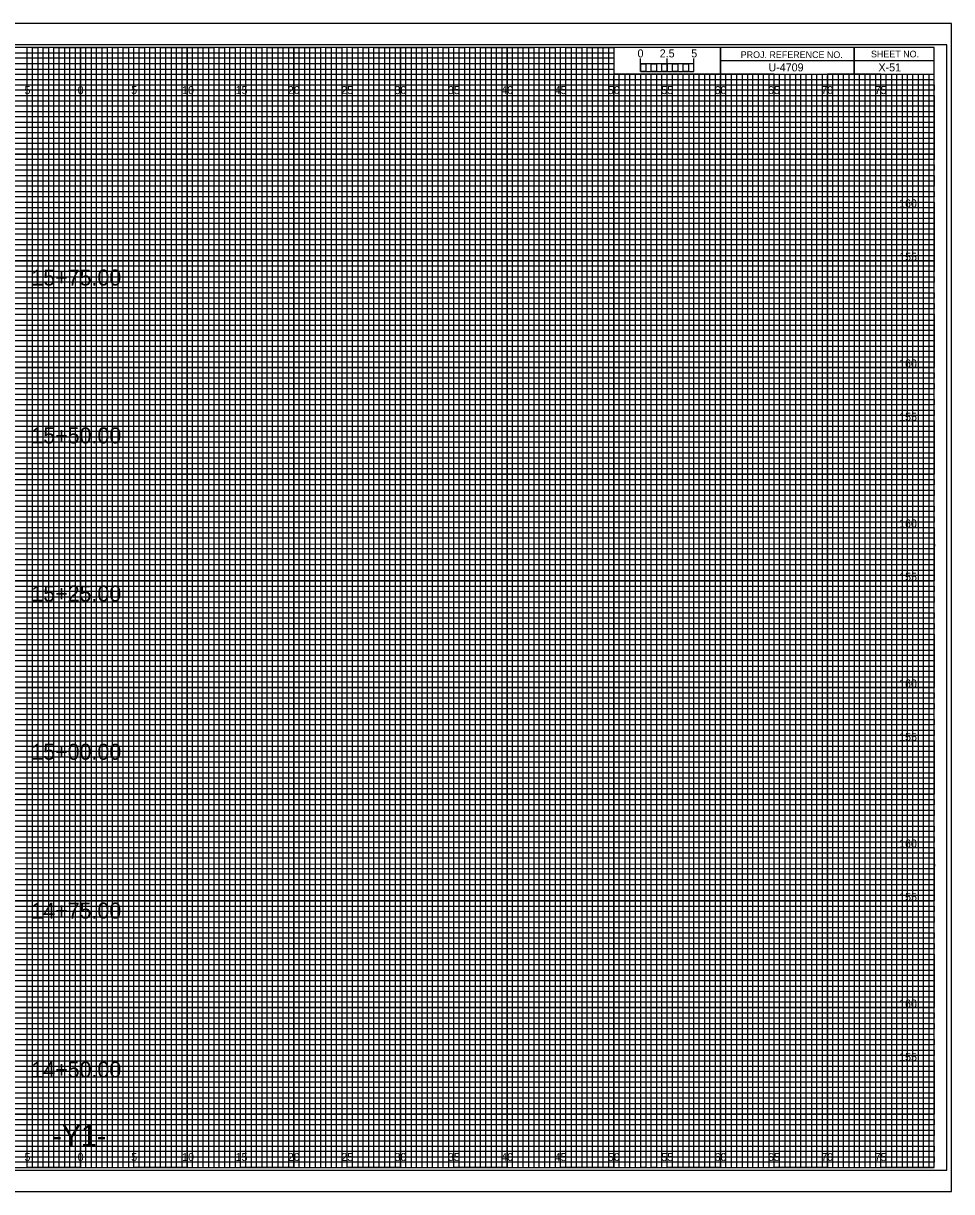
# Model space of a CAD drawing. Extents: x -7 to 162, y 328 to 437.
# Drawn here: x 74.6 to 161.7, y 327.7 to 437.2 of the extents above; entities that cross this region are included whole.
import ezdxf

# ---------------------------------------------------------------- set-up
doc = ezdxf.new("R2010")
doc.units = 0
for name, color, linetype in [('Prop CMT Conc Surface', 7, 'Continuous'), ('Prop CMT Pvmt Course 1', 7, 'Continuous'), ('Prop CMT Pvmt Surface Shoulder', 7, 'Continuous'), ('Prop CMT Pvmt Wedge Surface 3', 7, 'Continuous'), ('Prop CMT Shld Paved Course 1', 7, 'Continuous'), ('Prop CMT Shld Paved Course 2', 7, 'Continuous'), ('Prop CMT Shld Paved Course 3', 7, 'Continuous'), ('Prop CMT Slope Grass', 7, 'Continuous'), ('Prop XS Alignment Label', 7, 'Continuous'), ('Prop XS Bar Scale Labels', 7, 'Continuous'), ('Prop XS Ditch Standard Text', 7, 'Continuous'), ('Prop XS Earthwork Shape', 7, 'Continuous'), ('Prop XS Hydro Elevations', 7, 'Continuous'), ('Prop XS Project Number', 7, 'Continuous'), ('Prop XS SE Text', 7, 'Continuous'), ('Prop XS Sheet Number', 7, 'Continuous'), ('Prop XS Side Slope Text', 7, 'Continuous')]:
    doc.layers.add(name, color=color, linetype=linetype)

msp = doc.modelspace()

# ---------------------------------------------------------------- linework, layer by layer
at = {"layer": 'Prop CMT Conc Surface'}
for points in [[(72.5, 330), (77.5, 330), (77.5, 435), (82.5, 435), (82.5, 330), (87.5, 330), (87.5, 435), (92.5, 435), (92.5, 330), (97.5, 330), (97.5, 435), (102.5, 435), (102.5, 330), (107.5, 330), (107.5, 435), (112.5, 435), (112.5, 330), (117.5, 330), (117.5, 435), (122.5, 435), (122.5, 330), (127.5, 330), (127.5, 435), (129.97, 435), (130, 435), (130, 432.5), (132.5, 432.5), (132.5, 330), (137.5, 330), (137.5, 432.5), (142.5, 432.5), (142.5, 330), (147.5, 330), (147.5, 432.5), (152.5, 432.5), (152.5, 330), (157.5, 330), (157.5, 432.5)], [(0, 432.5), (137.5, 432.5)], [(0, 422.5), (160, 422.5), (160, 427.5), (0, 427.5)], [(0, 412.5), (160, 412.5), (160, 417.5), (0, 417.5)], [(0, 402.5), (160, 402.5), (160, 407.5), (0, 407.5)], [(0, 392.5), (160, 392.5), (160, 397.5), (0, 397.5)], [(0, 382.5), (160, 382.5), (160, 387.5), (0, 387.5)], [(0, 372.5), (160, 372.5), (160, 377.5), (0, 377.5)], [(0, 362.5), (160, 362.5), (160, 367.5), (0, 367.5)], [(0, 352.5), (160, 352.5), (160, 357.5), (0, 357.5)], [(0, 342.5), (160, 342.5), (160, 347.5), (0, 347.5)], [(0, 332.5), (160, 332.5), (160, 337.5), (0, 337.5)]]:
    msp.add_lwpolyline(points, dxfattribs=at)
at = {"layer": 'Prop CMT Pvmt Course 1'}
for p, q in [((75, 435), (70, 435)), ((75, 330), (75, 435)), ((85, 435), (80, 435)), ((80, 435), (80, 330)), ((85, 330), (85, 435)), ((95, 435), (90, 435)), ((90, 435), (90, 330)), ((95, 330), (95, 435)), ((105, 435), (100, 435)), ((100, 435), (100, 330)), ((105, 330), (105, 435)), ((115, 435), (110, 435)), ((110, 435), (110, 330)), ((115, 330), (115, 435)), ((125, 435), (120, 435)), ((120, 435), (120, 330)), ((125, 330), (125, 435)), ((130, 435), (130, 330)), ((135, 330), (135, 432.5)), ((145, 432.5), (140, 432.5)), ((140, 432.5), (140, 330)), ((145, 330), (145, 432.5)), ((155, 432.5), (150, 432.5)), ((150, 432.5), (150, 330)), ((155, 330), (155, 432.5)), ((80, 330), (75, 330)), ((90, 330), (85, 330)), ((100, 330), (95, 330)), ((110, 330), (105, 330)), ((120, 330), (115, 330)), ((130, 330), (125, 330)), ((140, 330), (135, 330)), ((150, 330), (145, 330)), ((160, 330), (155, 330)), ((160, 330), (160, 330))]:
    msp.add_line(p, q, dxfattribs=at)
for points in [[(0, 430), (160, 430), (160, 425), (0, 425)], [(0, 420), (160, 420), (160, 415), (0, 415)], [(0, 410), (160, 410), (160, 405), (0, 405)], [(0, 400), (160, 400), (160, 395), (0, 395)], [(0, 390), (160, 390), (160, 385), (0, 385)], [(0, 380), (160, 380), (160, 375), (0, 375)], [(0, 370), (160, 370), (160, 365), (0, 365)], [(0, 360), (160, 360), (160, 355), (0, 355)], [(0, 350), (160, 350), (160, 345), (0, 345)], [(0, 340), (160, 340), (160, 335), (0, 335)]]:
    msp.add_lwpolyline(points, dxfattribs=at)
at = {"layer": 'Prop CMT Pvmt Surface Shoulder'}
msp.add_lwpolyline([(-6.7, 327.75), (161.65, 327.75), (161.65, 437.25), (-6.7, 437.25)], close=True, dxfattribs=at)
at = {"layer": 'Prop CMT Shld Paved Course 1'}
for p, q in [((152.5, 435), (152.5, 432.5)), ((152.5, 432.5), (152.5, 435)), ((160, 433.75), (140, 433.75)), ((140, 433.75), (140, 432.5)), ((140, 432.5), (160, 432.5))]:
    msp.add_line(p, q, dxfattribs=at)
for points in [[(160, 435), (0, 435), (0, 330), (160, 330)], [(140, 435), (130, 435), (130, 432.51), (140, 432.51)], [(160, 435), (140, 435), (140, 432.5), (160, 432.5)]]:
    msp.add_lwpolyline(points, close=True, dxfattribs=at)
at = {"layer": 'Prop CMT Shld Paved Course 2'}
for p, q in [((133.5, 432.5), (133, 432.5)), ((133, 432.5), (133, 330)), ((133.5, 330), (133.5, 432.5)), ((134.5, 432.5), (134, 432.5)), ((134, 432.5), (134, 330)), ((134.5, 330), (134.5, 432.5)), ((133, 330), (132.5, 330)), ((134, 330), (133.5, 330))]:
    msp.add_line(p, q, dxfattribs=at)
for points in [[(75, 330), (75.5, 330), (75.5, 435), (76, 435), (76, 330)], [(76, 330), (76.5, 330), (76.5, 435), (77, 435), (77, 330)], [(77.5, 330), (78, 330), (78, 435), (78.5, 435), (78.5, 330)], [(78.5, 330), (79, 330), (79, 435), (79.5, 435), (79.5, 330)], [(80, 330), (80.5, 330), (80.5, 435), (81, 435), (81, 330)], [(81, 330), (81.5, 330), (81.5, 435), (82, 435), (82, 330)], [(82.5, 330), (83, 330), (83, 435), (83.5, 435), (83.5, 330)], [(83.5, 330), (84, 330), (84, 435), (84.5, 435), (84.5, 330)], [(85, 330), (85.5, 330), (85.5, 435), (86, 435), (86, 330)], [(86, 330), (86.5, 330), (86.5, 435), (87, 435), (87, 330)], [(87.5, 330), (88, 330), (88, 435), (88.5, 435), (88.5, 330)], [(88.5, 330), (89, 330), (89, 435), (89.5, 435), (89.5, 330)], [(90, 330), (90.5, 330), (90.5, 435), (91, 435), (91, 330)], [(91, 330), (91.5, 330), (91.5, 435), (92, 435), (92, 330)], [(92.5, 330), (93, 330), (93, 435), (93.5, 435), (93.5, 330)], [(93.5, 330), (94, 330), (94, 435), (94.5, 435), (94.5, 330)], [(95, 330), (95.5, 330), (95.5, 435), (96, 435), (96, 330)], [(96, 330), (96.5, 330), (96.5, 435), (97, 435), (97, 330)], [(97.5, 330), (98, 330), (98, 435), (98.5, 435), (98.5, 330)], [(98.5, 330), (99, 330), (99, 435), (99.5, 435), (99.5, 330)], [(100, 330), (100.5, 330), (100.5, 435), (101, 435), (101, 330)], [(101, 330), (101.5, 330), (101.5, 435), (102, 435), (102, 330)], [(102.5, 330), (103, 330), (103, 435), (103.5, 435), (103.5, 330)], [(103.5, 330), (104, 330), (104, 435), (104.5, 435), (104.5, 330)], [(105, 330), (105.5, 330), (105.5, 435), (106, 435), (106, 330)], [(106, 330), (106.5, 330), (106.5, 435), (107, 435), (107, 330)], [(107.5, 330), (108, 330), (108, 435), (108.5, 435), (108.5, 330)], [(108.5, 330), (109, 330), (109, 435), (109.5, 435), (109.5, 330)], [(110, 330), (110.5, 330), (110.5, 435), (111, 435), (111, 330)], [(111, 330), (111.5, 330), (111.5, 435), (112, 435), (112, 330)], [(112.5, 330), (113, 330), (113, 435), (113.5, 435), (113.5, 330)], [(113.5, 330), (114, 330), (114, 435), (114.5, 435), (114.5, 330)], [(115, 330), (115.5, 330), (115.5, 435), (116, 435), (116, 330)], [(116, 330), (116.5, 330), (116.5, 435), (117, 435), (117, 330)], [(117.5, 330), (118, 330), (118, 435), (118.5, 435), (118.5, 330)], [(118.5, 330), (119, 330), (119, 435), (119.5, 435), (119.5, 330)], [(120, 330), (120.5, 330), (120.5, 435), (121, 435), (121, 330)], [(121, 330), (121.5, 330), (121.5, 435), (122, 435), (122, 330)], [(122.5, 330), (123, 330), (123, 435), (123.5, 435), (123.5, 330)], [(123.5, 330), (124, 330), (124, 435), (124.5, 435), (124.5, 330)], [(125, 330), (125.5, 330), (125.5, 435), (126, 435), (126, 330)], [(126, 330), (126.5, 330), (126.5, 435), (127, 435), (127, 330)], [(127.5, 330), (128, 330), (128, 435), (128.5, 435), (128.5, 330)], [(128.5, 330), (129, 330), (129, 435), (129.5, 435), (129.5, 330)], [(130, 330), (130.5, 330), (130.5, 432.5), (131.01, 432.5), (131.01, 330)], [(131, 330), (131.5, 330), (131.5, 432.5), (132, 432.5), (132, 330)], [(135, 330), (135.49, 330), (135.49, 432.5), (136, 432.5), (136, 330)], [(136, 330), (136.5, 330), (136.5, 432.5), (137.03, 432.5), (137.03, 330)], [(137.5, 330), (138, 330), (138, 432.5), (138.5, 432.5), (138.5, 330)], [(138.5, 330), (139, 330), (139, 432.5), (139.5, 432.5), (139.5, 330)], [(140, 330), (140.5, 330), (140.5, 432.5), (141, 432.5), (141, 330)], [(141, 330), (141.5, 330), (141.5, 432.5), (142, 432.5), (142, 330)], [(142.5, 330), (143, 330), (143, 432.5), (143.5, 432.5), (143.5, 330)], [(143.5, 330), (144, 330), (144, 432.5), (144.5, 432.5), (144.5, 330)], [(145, 330), (145.5, 330), (145.5, 432.5), (146, 432.5), (146, 330)], [(146, 330), (146.5, 330), (146.5, 432.5), (147, 432.5), (147, 330)], [(147.5, 330), (148, 330), (148, 432.5), (148.5, 432.5), (148.5, 330)], [(148.5, 330), (149, 330), (149, 432.5), (149.5, 432.5), (149.5, 330)], [(150, 330), (150.5, 330), (150.5, 432.5), (151, 432.5), (151, 330)], [(151, 330), (151.5, 330), (151.5, 432.5), (152, 432.5), (152, 330)], [(152.5, 330), (153, 330), (153, 432.5), (153.5, 432.5), (153.5, 330)], [(153.5, 330), (154, 330), (154, 432.5), (154.5, 432.5), (154.5, 330)], [(155, 330), (155.5, 330), (155.5, 432.5), (156, 432.5), (156, 330)], [(156, 330), (156.5, 330), (156.5, 432.5), (157, 432.5), (157, 330)], [(157.5, 330), (158, 330), (158, 432.5), (158.5, 432.5), (158.5, 330)], [(158.5, 330), (159, 330), (159, 432.5), (159.5, 432.5), (159.5, 330)]]:
    msp.add_lwpolyline(points, dxfattribs=at)
at = {"layer": 'Prop CMT Shld Paved Course 3'}
for p, q in [((132.5, 432.75), (132.5, 433.95)), ((132.5, 433.45), (132.5, 433.95)), ((135, 432.75), (135, 433.95)), ((137.5, 432.75), (137.5, 433.95)), ((137.5, 433.45), (137.5, 433.95))]:
    msp.add_line(p, q, dxfattribs=at)
for points in [[(137.5, 433.45), (132.5, 433.45), (132.5, 432.75), (137.5, 432.75)], [(132.5, 433.45), (133, 433.45), (133, 432.75), (132.5, 432.75)], [(133.5, 433.45), (134, 433.45), (134, 432.75), (133.5, 432.75)], [(134.5, 433.45), (135, 433.45), (135, 432.75), (134.5, 432.75)], [(135.5, 433.45), (136, 433.45), (136, 432.75), (135.5, 432.75)], [(136.5, 433.45), (137, 433.45), (137, 432.75), (136.5, 432.75)]]:
    msp.add_lwpolyline(points, close=True, dxfattribs=at)
at = {"layer": 'Prop CMT Slope Grass'}
for p, q in [((0, 434.5), (130, 434.5)), ((130, 433.99), (0, 433.99)), ((130, 434.5), (130, 433.99)), ((0, 433.5), (130, 433.5)), ((130, 432.94), (0, 432.94)), ((130, 433.5), (130, 432.94)), ((0, 432), (160, 432))]:
    msp.add_line(p, q, dxfattribs=at)
for points in [[(0, 431.5), (135, 431.5), (160, 431.5), (160, 431), (0, 431)], [(0, 430.5), (160, 430.5), (160, 429.5), (0, 429.5)], [(0, 429), (160, 429), (160, 428.5), (0, 428.49)], [(0, 428), (160, 428), (160, 427), (0, 427)], [(0, 426.5), (160, 426.5), (160, 426), (0, 426)], [(0, 425.5), (160, 425.5), (160, 424.5), (0, 424.5)], [(0, 424), (160, 424), (160, 423.5), (0, 423.5)], [(0, 423), (160, 423), (160, 422), (0, 422)], [(0, 421.5), (160, 421.5), (160, 421), (0, 421)], [(0, 420.5), (160, 420.5), (160, 419.5), (0, 419.5)], [(0, 419), (160, 419), (160, 418.5), (0, 418.5)], [(0, 418), (160, 418), (160, 416.98), (160, 416.5), (160, 416), (0, 416)], [(0, 417), (160, 417), (160, 416.5), (0, 416.5)], [(0, 415.5), (160, 415.5), (160, 414.5), (0, 414.51)], [(0, 414.51), (160, 414.5), (160, 414), (0, 414)], [(0, 413.5), (160, 413.5), (160, 413), (0, 413)], [(0, 412), (160, 412), (160, 411.5), (0, 411.5)], [(0, 411), (160, 411), (160, 410.5), (0, 410.5)], [(-0.04, 409.44), (160, 409.44), (160, 408.94), (-0.04, 408.94)], [(0, 408.5), (160, 408.5), (160, 408), (0, 408)], [(0, 407), (160, 407), (160, 406.5), (0, 406.5)], [(0, 406), (160, 406), (160, 405.5), (0, 405.5)], [(0, 404.5), (160, 404.5), (160, 404), (0, 404)], [(0, 403.5), (160, 403.5), (160, 403), (0, 403)], [(0, 402), (160, 402), (160, 401.5), (0, 401.5)], [(0, 401), (160, 401), (160, 400.5), (0, 400.5)], [(0, 399.5), (160, 399.5), (160, 398.99), (0, 399)], [(0, 398.5), (160, 398.5), (160, 398), (0, 398)], [(0, 397), (160, 397), (160, 396.5), (0, 396.5)], [(0, 396), (160, 396), (160, 395.5), (0, 395.5)], [(0, 394.5), (160, 394.5), (160, 394), (0, 394)], [(0, 393.5), (160, 393.5), (160, 393), (0, 393)], [(0, 392), (160, 392), (160, 391.5), (0, 391.5)], [(0, 391), (160, 391), (160, 390.5), (0, 390.5)], [(0, 389.5), (160, 389.5), (160, 389), (0, 389)], [(0, 388.5), (160.03, 388.45), (160, 388), (0, 388)], [(0, 387), (160, 387), (160, 386.5), (0, 386.5)], [(0, 386), (160, 386), (160, 385.5), (0, 385.5)], [(0, 384.5), (160, 384.5), (160, 384), (0, 384)], [(0, 383.5), (160, 383.5), (160, 383), (0, 383)], [(0, 382), (160, 382), (160, 381.5), (0, 381.5)], [(0, 381), (160, 381), (160, 380.5), (0, 380.5)], [(0, 379.5), (160, 379.5), (160, 379), (0, 379)], [(0, 378.5), (160, 378.5), (160, 378), (0, 378)], [(0, 377), (160, 377), (160, 376.5), (0, 376.5)], [(0, 376), (160, 376), (160, 375.5), (0, 375.5)], [(0, 374.5), (160, 374.5), (160, 374), (0, 374)], [(0, 373.5), (160, 373.5), (160, 373), (0, 373)], [(0, 372), (160, 372), (160, 371.5), (0, 371.5)], [(0, 371), (160, 371), (160, 370.5), (0, 370.5)], [(0, 369.5), (160, 369.5), (160, 368.99), (0, 369)], [(0, 368.5), (160, 368.5), (160, 368), (0, 368)], [(0, 367), (160, 367), (160, 366.5), (0, 366.5)], [(0, 366), (160, 366), (160, 365.5), (0, 365.5)], [(0, 364.5), (160, 364.5), (160, 364), (0, 364)], [(0, 363.5), (160, 363.5), (160, 363), (0, 363)], [(0, 362), (160, 362), (160, 361.5), (0, 361.5)], [(0, 361), (160, 361), (160, 360.5), (0, 360.5)], [(0, 359.5), (160, 359.5), (160, 359), (0, 359)], [(0, 358.5), (160.03, 358.45), (160, 358), (0, 358)], [(0, 357), (160, 357), (160, 356.5), (0, 356.5)], [(0, 356), (160, 356), (160, 355.5), (0, 355.5)], [(0, 354.5), (160, 354.5), (160, 354), (0, 354)], [(0, 353.5), (160, 353.5), (160, 353), (0, 353)], [(0, 352), (160, 352), (160, 351.5), (0, 351.5)], [(0, 351), (160, 351), (160, 350.5), (0, 350.5)], [(0, 349.5), (160, 349.5), (160, 349), (0, 349)], [(0, 348.5), (160, 348.5), (160, 348), (0, 348)], [(0, 347), (160, 347), (160, 346.5), (0, 346.5)], [(0, 346), (160, 346), (160, 345.5), (0, 345.5)], [(0, 344.5), (160, 344.5), (160, 344), (0, 344)], [(0, 343.5), (160, 343.5), (160, 343), (0, 343)], [(0, 342), (160, 342), (160, 341.5), (0, 341.5)], [(0, 341), (160, 341), (160, 340.5), (0, 340.5)], [(0, 339.5), (160, 339.5), (160, 339), (0, 339)], [(0, 338.5), (160, 338.5), (160, 338), (0, 338)], [(0, 337), (160, 337), (160, 336.5), (0, 336.5)], [(0, 336), (160, 336), (160, 335.5), (0, 335.5)], [(0, 334.5), (160, 334.5), (160, 334), (0, 334)], [(0, 333.5), (160, 333.5), (160, 333), (0, 333)], [(0, 332), (160, 332), (160, 331.5), (0, 331.5)], [(0, 331), (160, 331), (160, 330.5), (0, 330.5)]]:
    msp.add_lwpolyline(points, dxfattribs=at)
at = {"layer": 'Prop XS Hydro Elevations'}
for p, q in [((161.65, 437.25), (-6.7, 437.25)), ((-6.7, 327.75), (161.65, 327.75))]:
    msp.add_line(p, q, dxfattribs=at)
at = {"layer": 'Prop XS SE Text'}
msp.add_lwpolyline([(-5.4, 329.75), (161.2, 329.75), (161.2, 435.25), (-5.4, 435.25)], close=True, dxfattribs=at)
at = {"layer": 'Prop XS Side Slope Text'}
for p, q in [((75, 330), (75, 435)), ((80, 330), (80, 435)), ((85, 330), (85, 435)), ((90, 330), (90, 435)), ((95, 330), (95, 435)), ((100, 330), (100, 435)), ((105, 330), (105, 435)), ((110, 330), (110, 435)), ((115, 330), (115, 435)), ((120, 330), (120, 435)), ((125, 330), (125, 435)), ((130, 330), (130, 432.34)), ((135, 330), (135, 432.34)), ((140, 330), (140, 432.34)), ((145, 330), (145, 432.34)), ((150, 330), (150, 432.34)), ((155, 330), (155, 432.34)), ((0, 430), (160, 430)), ((0, 425), (160, 425)), ((0, 420), (160, 420)), ((0, 415), (160, 415)), ((0, 410), (160, 410)), ((0, 405), (160, 405)), ((0, 400), (160, 400)), ((0, 395), (160, 395)), ((0, 390), (160, 390)), ((0, 385), (160, 385)), ((0, 380), (160, 380)), ((0, 375), (160, 375)), ((0, 370), (160, 370)), ((0, 365), (160, 365)), ((0, 360), (160, 360)), ((0, 355), (160, 355)), ((0, 350), (160, 350)), ((0, 345), (160, 345)), ((0, 340), (160, 340)), ((0, 335), (160, 335))]:
    msp.add_line(p, q, dxfattribs=at)

# ---------------------------------------------------------------- texts
at = {"layer": 'Prop CMT Pvmt Wedge Surface 3'}
for s, p in [('5', (74.74, 430.62)), ('0', (79.73, 430.62)), ('0', (79.73, 430.62)), ('5', (84.74, 430.62)), ('10', (89.52, 430.62)), ('15', (94.53, 430.62)), ('20', (99.43, 430.62)), ('25', (104.44, 430.62)), ('30', (109.43, 430.62)), ('35', (114.44, 430.62)), ('40', (119.43, 430.62)), ('45', (124.44, 430.62)), ('50', (129.43, 430.62)), ('55', (134.44, 430.62)), ('60', (139.43, 430.62)), ('65', (144.44, 430.62)), ('70', (149.43, 430.62)), ('75', (154.44, 430.62)), ('5', (74.74, 330.62)), ('0', (79.73, 330.62)), ('0', (79.73, 330.62)), ('5', (84.74, 330.62)), ('10', (89.52, 330.62)), ('15', (94.53, 330.62)), ('20', (99.43, 330.62)), ('25', (104.44, 330.62)), ('30', (109.43, 330.62)), ('35', (114.44, 330.62)), ('40', (119.43, 330.62)), ('45', (124.44, 330.62)), ('50', (129.43, 330.62)), ('55', (134.44, 330.62)), ('60', (139.43, 330.62)), ('65', (144.44, 330.62)), ('70', (149.43, 330.62)), ('75', (154.44, 330.62))]:
    msp.add_text(s, height=0.75, dxfattribs=at).set_placement(p)
at = {"layer": 'Prop CMT Shld Paved Course 1'}
for s, p in [('PROJ. REFERENCE NO.', (141.88, 434)), ('SHEET NO.', (154.09, 434.06))]:
    msp.add_text(s, height=0.625, dxfattribs=at).set_placement(p)
at = {"layer": 'Prop CMT Shld Paved Course 3'}
msp.add_text('0', height=0.75, dxfattribs=at).set_placement((132.21, 434.06))
at = {"layer": 'Prop XS Alignment Label'}
msp.add_text('-Y1-', height=2, dxfattribs=at).set_placement((77.36, 332))
at = {"layer": 'Prop XS Bar Scale Labels'}
for s, p in [('2.5', (134.29, 434.06)), ('5', (137.24, 434.06))]:
    msp.add_text(s, height=0.75, dxfattribs=at).set_placement(p)
at = {"layer": 'Prop XS Ditch Standard Text'}
for s, p in [('160', (156.72, 420)), ('155', (156.73, 415)), ('160', (156.72, 405)), ('155', (156.73, 400)), ('160', (156.72, 390)), ('155', (156.73, 385)), ('160', (156.72, 375)), ('155', (156.73, 370)), ('160', (156.72, 360)), ('155', (156.73, 355)), ('160', (156.72, 345)), ('155', (156.73, 340))]:
    msp.add_text(s, height=0.75, dxfattribs=at).set_placement(p)
at = {"layer": 'Prop XS Earthwork Shape'}
for s, p in [('15+75.00', (75.39, 412.68)), ('15+50.00', (75.39, 397.88)), ('15+25.00', (75.39, 383.06)), ('15+00.00', (75.39, 368.23)), ('14+75.00', (75.39, 353.34)), ('14+50.00', (75.39, 338.44))]:
    msp.add_text(s, height=1.5, dxfattribs=at).set_placement(p)
at = {"layer": 'Prop XS Project Number'}
msp.add_text('U-4709', height=0.75, dxfattribs=at).set_placement((144.48, 432.75))
at = {"layer": 'Prop XS Sheet Number'}
msp.add_text('X-51', height=0.75, dxfattribs=at).set_placement((154.79, 432.75))

doc.saveas('drawing.dxf')
